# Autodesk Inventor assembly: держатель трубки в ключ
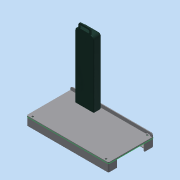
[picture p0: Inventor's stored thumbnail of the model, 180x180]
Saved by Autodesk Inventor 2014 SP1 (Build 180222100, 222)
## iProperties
Created: 2015-10
Part Number: держатель трубки в ключ
Document SubType Name: Assembly
Designer: hals
Author: hals
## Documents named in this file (8)
- F:\yandex\models 3D\держатель трубки в ключ.iam
- F:\yandex\models 3D\держатель трубки в ключ.ipt
- F:\yandex\models 3D\держатель трубки в ключ - панелька.ipt
- F:\yandex\models 3D\держатель для трубки в ключ обечайка.ipt
- F:\yandex\models 3D\держатель трубки в ключ\Мастер проектирования\Болтовое соединение2.iam
- F:\yandex\models 3D\держатель трубки в ключ\Мастер проектирования\Болтовое соединение3.iam
- F:\yandex\models 3D\держатель для трубки в ключ обечайка угол.ipt
- F:\yandex\models 3D\держатель трубки в ключ\Мастер проектирования\Болтовое соединение4.iam
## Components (7 placed, 5 different names)
1. держатель трубки в ключ:1 — Совмещение:1, Совмещение:2, Совмещение:3
2. держатель трубки в ключ - панелька:1 — Совмещение:1, Совмещение:2, Совмещение:3, Заподлицо:1, Заподлицо:2, Совмещение:5, Совмещение:8, Заподлицо:3, Заподлицо:4, Совмещение:9
3. держатель для трубки в ключ обечайка:1 — Заподлицо:1, Заподлицо:2, Совмещение:4, Совмещение:6, Совмещение:7
4. Болтовое соединение:1 [sub-assembly] — Совмещение:4, Совмещение:5
5. Болтовое соединение:2 [sub-assembly] — Совмещение:6, Совмещение:7
6. держатель для трубки в ключ обечайка угол:1 — Совмещение:8, Заподлицо:3, Заподлицо:4, Совмещение:10
7. Болтовое соединение:3 [sub-assembly] — Совмещение:9, Совмещение:10
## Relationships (14: Mate 10, Flush 4)
- Совмещение:1 [Mate]: держатель трубки в ключ:1 ↔ держатель трубки в ключ - панелька:1
- Совмещение:2 [Mate]: держатель трубки в ключ:1 ↔ держатель трубки в ключ - панелька:1
- Совмещение:3 [Mate]: держатель трубки в ключ:1 ↔ держатель трубки в ключ - панелька:1
- Заподлицо:1 [Flush]: держатель трубки в ключ - панелька:1 ↔ держатель для трубки в ключ обечайка:1
- Заподлицо:2 [Flush]: держатель трубки в ключ - панелька:1 ↔ держатель для трубки в ключ обечайка:1
- Совмещение:4 [Mate]: держатель для трубки в ключ обечайка:1 ↔ Болтовое соединение:1
- Совмещение:5 [Mate]: держатель трубки в ключ - панелька:1 ↔ Болтовое соединение:1
- Совмещение:6 [Mate]: держатель для трубки в ключ обечайка:1 ↔ Болтовое соединение:2
- Совмещение:7 [Mate]: держатель для трубки в ключ обечайка:1 ↔ Болтовое соединение:2
- Совмещение:8 [Mate]: держатель трубки в ключ - панелька:1 ↔ держатель для трубки в ключ обечайка угол:1
- Заподлицо:3 [Flush]: держатель трубки в ключ - панелька:1 ↔ держатель для трубки в ключ обечайка угол:1
- Заподлицо:4 [Flush]: держатель трубки в ключ - панелька:1 ↔ держатель для трубки в ключ обечайка угол:1
- Совмещение:9 [Mate]: держатель трубки в ключ - панелька:1 ↔ Болтовое соединение:3
- Совмещение:10 [Mate]: держатель для трубки в ключ обечайка угол:1 ↔ Болтовое соединение:3
